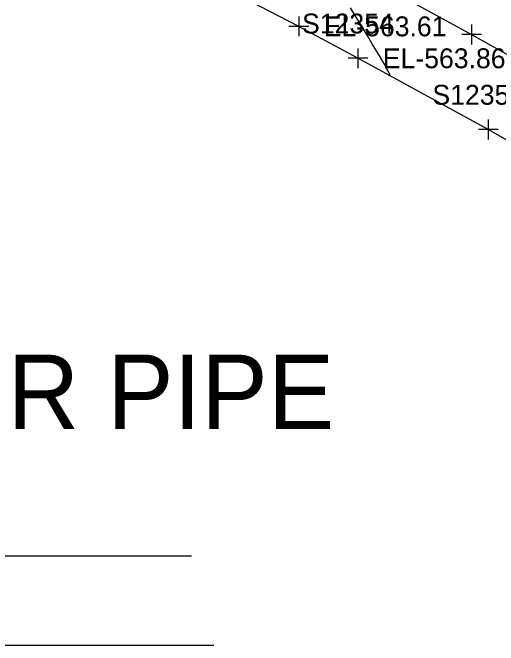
# Model space of a CAD drawing. Extents: x 1729869 to 1735532, y 648588 to 653771.
# Drawn here: x 1730581.4 to 1730679.1, y 652329.3 to 652456.6 of the extents above; entities that cross this region are included whole.
import ezdxf

# ---------------------------------------------------------------- set-up
doc = ezdxf.new("R2010")
doc.units = 0
for name, color, linetype in [('SURVEY - CONTOURS - Intermediate with optional Text', 7, 'Continuous'), ('SURVEY - DRAINAGE - Area Shapes Text', 7, 'Continuous'), ('SURVEY - TRANSPORTATION - Roads', 7, 'Continuous'), ('SURVEY - TRANSPORTATION - Roads - Points - Elevations', 7, 'Continuous'), ('SURVEY - TRANSPORTATION - Roads - Points - Locators', 7, 'Continuous'), ('SURVEY - TRANSPORTATION - Roads - Points - Numbers', 7, 'Continuous')]:
    doc.layers.add(name, color=color, linetype=linetype)

msp = doc.modelspace()

# ---------------------------------------------------------------- linework, layer by layer
at = {"layer": 'SURVEY - CONTOURS - Intermediate with optional Text'}
msp.add_lwpolyline([(1730657.07, 652444.04), (1730657.15, 652444), (1730657.19, 652443.98), (1730657.22, 652443.97), (1730657.25, 652443.96), (1730657.28, 652443.96), (1730657.32, 652444.01), (1730657.3, 652444.13), (1730657.22, 652444.32), (1730657.11, 652444.57), (1730656.96, 652444.87), (1730656.78, 652445.2), (1730656.5, 652445.7), (1730656.2, 652446.24), (1730655.88, 652446.79), (1730655.2, 652447.96), (1730654.5, 652449.14), (1730653.76, 652450.39), (1730652.71, 652452.13), (1730649.39, 652457.63)], dxfattribs=at)
at = {"layer": 'SURVEY - DRAINAGE - Area Shapes Text'}
for p, q in [((1730467.1, 652347.33), (1730617.4, 652347.33)), ((1730485.95, 652329.33), (1730621.9, 652329.33))]:
    msp.add_line(p, q, dxfattribs=at)
at = {"layer": 'SURVEY - TRANSPORTATION - Roads'}
for points in [[(1730649.22, 652465.7), (1730673.76, 652452.23), (1730705.2, 652434.69), (1730734.58, 652417.59), (1730758.51, 652403.05), (1730784.01, 652387.26), (1730797.56, 652378.75), (1730819.41, 652364.67), (1730822.77, 652362.5)], [(1730842.71, 652331.09), (1730807.69, 652354.26), (1730790.84, 652365.03), (1730779.05, 652372.57), (1730768.87, 652378.93), (1730733.06, 652400.86), (1730706.47, 652416.41), (1730677.11, 652433.11), (1730650.89, 652447.45), (1730639.01, 652453.88), (1730623.05, 652462.2)]]:
    msp.add_lwpolyline(points, dxfattribs=at)
at = {"layer": 'SURVEY - TRANSPORTATION - Roads - Points - Locators'}
for p, q in [((1730639.01, 652455.88), (1730639.01, 652451.88)), ((1730641.01, 652453.88), (1730637.01, 652453.88)), ((1730673.76, 652454.23), (1730673.76, 652450.23)), ((1730675.76, 652452.23), (1730671.76, 652452.23)), ((1730650.89, 652449.45), (1730650.89, 652445.45)), ((1730652.89, 652447.45), (1730648.89, 652447.45)), ((1730677.11, 652435.11), (1730677.11, 652431.11)), ((1730679.11, 652433.11), (1730675.11, 652433.11))]:
    msp.add_line(p, q, dxfattribs=at)

# ---------------------------------------------------------------- texts
at = {"layer": 'SURVEY - DRAINAGE - Area Shapes Text'}
msp.add_text('DRAINAGE DATA FOR PIPE', height=15, dxfattribs=at).set_placement((1730383.1, 652372.83))
at = {"layer": 'SURVEY - TRANSPORTATION - Roads - Points - Elevations'}
for s, p in [('EL-563.61', (1730644.01, 652451.88)), ('EL-563.86', (1730655.89, 652445.45))]:
    msp.add_text(s, height=4, dxfattribs=at).set_placement(p)
at = {"layer": 'SURVEY - TRANSPORTATION - Roads - Points - Numbers'}
for s, p in [('S12354', (1730639.65, 652452.45)), ('S12353', (1730665.87, 652438.11))]:
    msp.add_text(s, height=4, dxfattribs=at).set_placement(p)

doc.saveas('drawing.dxf')
